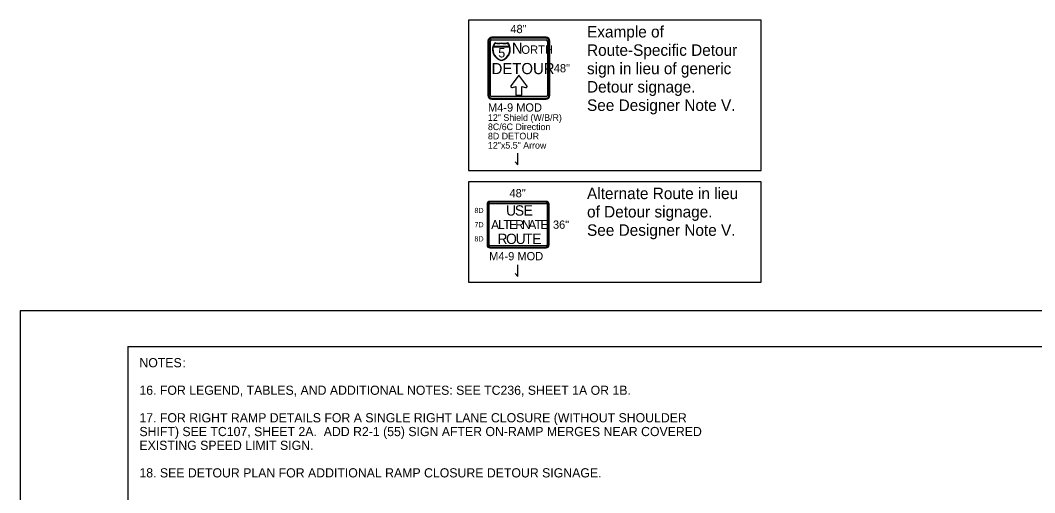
# Model space of a CAD drawing. Extents: x 99999 to 100116, y 99995 to 100013.
# Drawn here: x 100039.06 to 100047.9, y 100009.1 to 100013.22 of the extents above; entities that cross this region are included whole.
import ezdxf

# ---------------------------------------------------------------- set-up
doc = ezdxf.new("R2010")
doc.units = 0
for name, color, linetype in [('SH_GI_GeneralNotesBodyText', 7, 'Continuous'), ('SH_GI_PlotLimits', 7, 'Continuous'), ('SH_GI_SheetBorder', 7, 'Continuous'), ('TR_SN_ConstructionSigns', 7, 'Continuous'), ('TR_WZ_WorkZoneDetails', 7, 'Continuous')]:
    doc.layers.add(name, color=color, linetype=linetype)

msp = doc.modelspace()

# ---------------------------------------------------------------- linework, layer by layer
at = {"layer": 'SH_GI_PlotLimits'}
msp.add_lwpolyline([(100039.0625, 99999.6875), (100056.0625, 99999.6875), (100056.0625, 100010.6875), (100039.0625, 100010.6875)], close=True, dxfattribs=at)
at = {"layer": 'SH_GI_SheetBorder'}
for q in [(100040, 100000), (100055.75, 100010.375)]:
    msp.add_line((100040, 100010.375), q, dxfattribs=at)
at = {"layer": 'TR_SN_ConstructionSigns'}
for p, q in [((100043.1354, 100013.0373), (100043.1354, 100012.5648)), ((100043.1438, 100013.0373), (100043.1438, 100012.5648)), ((100043.1579, 100012.5648), (100043.1579, 100013.0373)), ((100043.6416, 100013.0711), (100043.1691, 100013.0711)), ((100043.6416, 100013.0626), (100043.1691, 100013.0626)), ((100043.1691, 100013.0486), (100043.6416, 100013.0486)), ((100043.6529, 100013.0373), (100043.6529, 100012.5648)), ((100043.6669, 100012.5648), (100043.6669, 100013.0373)), ((100043.6754, 100012.5648), (100043.6754, 100013.0373)), ((100043.3228, 100012.9875), (100043.1823, 100012.9875)), ((100043.1823, 100012.9875), (100043.3228, 100012.9875)), ((100043.1834, 100012.9912), (100043.3217, 100012.9912)), ((100043.3217, 100012.9912), (100043.1834, 100012.9912)), ((100043.6416, 100012.5536), (100043.1691, 100012.5536)), ((100043.1691, 100012.5395), (100043.6416, 100012.5395)), ((100043.1691, 100012.5311), (100043.6416, 100012.5311)), ((100043.6424, 100011.6405), (100043.153, 100011.6405)), ((100043.6424, 100011.6335), (100043.153, 100011.6335)), ((100043.153, 100011.6236), (100043.6424, 100011.6236)), ((100043.1277, 100011.6152), (100043.1277, 100011.2608)), ((100043.1347, 100011.6152), (100043.1347, 100011.2608)), ((100043.1446, 100011.2608), (100043.1446, 100011.6152)), ((100043.6508, 100011.6152), (100043.6508, 100011.2608)), ((100043.6607, 100011.2608), (100043.6607, 100011.6152)), ((100043.6677, 100011.2608), (100043.6677, 100011.6152)), ((100043.6424, 100011.2524), (100043.153, 100011.2524)), ((100043.153, 100011.2425), (100043.6424, 100011.2425)), ((100043.153, 100011.2355), (100043.6424, 100011.2355))]:
    msp.add_line(p, q, dxfattribs=at)
msp.add_lwpolyline([(100043.3367, 100012.6494), (100043.3356, 100012.6478), (100043.335, 100012.6461), (100043.3347, 100012.6441), (100043.3348, 100012.6424), (100043.335, 100012.6412), (100043.3356, 100012.6398), (100043.3373, 100012.6375), (100043.3386, 100012.6364), (100043.34, 100012.6355), (100043.3417, 100012.6348), (100043.3432, 100012.6345), (100043.3447, 100012.6343), (100043.3465, 100012.6343), (100043.3478, 100012.6346), (100043.3795, 100012.6424), (100043.3795, 100012.5671), (100043.4307, 100012.5671), (100043.4307, 100012.6429), (100043.4617, 100012.6337), (100043.4647, 100012.6331), (100043.4681, 100012.6334), (100043.4703, 100012.6342), (100043.4733, 100012.6362), (100043.4752, 100012.6389), (100043.476, 100012.6414), (100043.4761, 100012.6436), (100043.4754, 100012.6463), (100043.4746, 100012.6477), (100043.4051, 100012.7405), (100043.3367, 100012.6494)], dxfattribs=at)
for centre, radius, start, end in [((100043.1691, 100013.0373), 0.0337, 90, 180), ((100043.1691, 100013.0373), 0.0253, 90, 180), ((100043.1691, 100013.0373), 0.0113, 90, 180), ((100043.6416, 100013.0373), 0.0338, 360, 90), ((100043.6416, 100013.0373), 0.0253, 360, 90), ((100043.6416, 100013.0373), 0.0113, 360, 90), ((100043.2725, 100012.9642), 0.0973, 142.16169, 258.18105), ((100043.2715, 100012.9633), 0.0925, 164.85517, 258.18105), ((100043.2715, 100012.9633), 0.0925, 164.85517, 258.18105), ((100043.2715, 100012.9633), 0.0925, 142.16169, 162.48397), ((100043.2715, 100012.9633), 0.0925, 142.16169, 162.48397), ((100043.2245, 100013.1212), 0.1014, 253.48525, 286.04538), ((100043.2259, 100013.1124), 0.0964, 253.48525, 286.04538), ((100043.2259, 100013.1124), 0.0964, 253.48525, 286.04538), ((100043.2806, 100013.1212), 0.1014, 253.95462, 286.51475), ((100043.2792, 100013.1124), 0.0964, 253.95462, 286.51475), ((100043.2792, 100013.1124), 0.0964, 253.95462, 286.51475), ((100043.2325, 100012.9642), 0.0974, 281.90384, 37.84925), ((100043.2335, 100012.9633), 0.0925, 281.90384, 15.1558), ((100043.2335, 100012.9633), 0.0925, 281.90384, 15.1558), ((100043.2335, 100012.9633), 0.0925, 17.52691, 37.84925), ((100043.2335, 100012.9633), 0.0925, 17.52691, 37.84925), ((100043.1691, 100012.5648), 0.0338, 180, 270), ((100043.1691, 100012.5648), 0.0253, 180, 270), ((100043.1691, 100012.5648), 0.0113, 180, 270), ((100043.6416, 100012.5648), 0.0337, 270, 360), ((100043.6416, 100012.5648), 0.0253, 270, 0), ((100043.6416, 100012.5648), 0.0113, 270, 0), ((100043.153, 100011.6152), 0.0253, 90, 180), ((100043.153, 100011.6152), 0.0183, 90, 180), ((100043.153, 100011.6152), 0.00844, 90, 180), ((100043.6424, 100011.6152), 0.0253, 360, 90), ((100043.6424, 100011.6152), 0.0183, 360, 90), ((100043.6424, 100011.6152), 0.00844, 360, 90), ((100043.153, 100011.2608), 0.0253, 180, 270), ((100043.153, 100011.2608), 0.0183, 180, 270), ((100043.153, 100011.2608), 0.00844, 180, 270), ((100043.6424, 100011.2608), 0.0253, 270, 360), ((100043.6424, 100011.2608), 0.0183, 270, 0), ((100043.6424, 100011.2608), 0.00844, 270, 0)]:
    msp.add_arc(centre, radius, start, end, dxfattribs=at)
at = {"layer": 'TR_WZ_WorkZoneDetails'}
for p, q in [((100043.3963, 100011.9605), (100043.3963, 100012.0605)), ((100043.3713, 100011.9855), (100043.3963, 100011.9605)), ((100043.3963, 100010.9875), (100043.3963, 100011.0875)), ((100043.3713, 100011.0125), (100043.3963, 100010.9875))]:
    msp.add_line(p, q, dxfattribs=at)
for points in [[(100042.9666, 100011.9105), (100045.5143, 100011.9105), (100045.5143, 100013.2191), (100042.9666, 100013.2191)], [(100042.9666, 100010.9375), (100045.5143, 100010.9375), (100045.5143, 100011.8105), (100042.9666, 100011.8105)]]:
    msp.add_lwpolyline(points, close=True, dxfattribs=at)

# ---------------------------------------------------------------- texts
at = {"layer": 'SH_GI_GeneralNotesBodyText'}
for s, p in [('NOTES', (100040.1, 100010.195)), (':', (100040.4743, 100010.195)), ('16. FOR LEGEND, TABLES, AND ADDITIONAL NOTES: SEE TC236, SHEET 1A OR 1B.', (100040.1, 100009.955)), ('17. FOR RIGHT RAMP DETAILS FOR A SINGLE RIGHT LANE CLOSURE (WITHOUT SHOULDER ', (100040.1, 100009.715)), ('SHIFT) SEE TC107, SHEET 2A.  ADD R2-1 (55) SIGN AFTER ON-RAMP MERGES NEAR COVERED ', (100040.1, 100009.595)), ('EXISTING SPEED LIMIT SIGN.', (100040.1, 100009.475)), ('18. SEE DETOUR PLAN FOR ADDITIONAL RAMP CLOSURE DETOUR SIGNAGE.', (100040.1, 100009.235))]:
    msp.add_text(s, height=0.08, rotation=360, dxfattribs=at).set_placement(p)
at = {"layer": 'TR_SN_ConstructionSigns'}
for s, height, p in [('48"', 0.072, (100043.3306, 100013.1071)), ('5', 0.081, (100043.2253, 100012.8951)), ('N', 0.0972, (100043.3432, 100012.9267)), ('ORTH', 0.0729, (100043.4264, 100012.9267)), ('DETOUR', 0.0972, (100043.1668, 100012.7497)), ('48"', 0.072, (100043.7086, 100012.7651)), ('M4-9 MOD', 0.072, (100043.1354, 100012.4231)), ('12" Shield (W/B/R)', 0.0576, (100043.1354, 100012.3424)), ('8C/6C Direction', 0.0576, (100043.1354, 100012.2618)), ('8D DETOUR', 0.0576, (100043.1354, 100012.1811)), ('12"x5.5" Arrow', 0.0576, (100043.1354, 100012.1005)), ('48"', 0.072, (100043.323, 100011.6765)), ('36"', 0.072, (100043.7015, 100011.402)), ('M4-9 MOD', 0.072, (100043.1457, 100011.1275))]:
    msp.add_text(s, height=height, rotation=360, dxfattribs=at).set_placement(p)
for s, height, p in [('8D', 0.045, (100043.018, 100011.5392)), ('U', 0.09, (100043.2933, 100011.5167)), ('S', 0.09, (100043.3698, 100011.5167)), ('E', 0.09, (100043.4463, 100011.5167)), ('7D', 0.045, (100043.018, 100011.4155)), ('A', 0.0787, (100043.1626, 100011.3986)), ('L', 0.0787, (100043.2241, 100011.3986)), ('T', 0.0787, (100043.269, 100011.3986)), ('E', 0.0787, (100043.3201, 100011.3986)), ('R', 0.0787, (100043.3737, 100011.3986)), ('N', 0.0787, (100043.4312, 100011.3986)), ('A', 0.0787, (100043.4863, 100011.3986)), ('T', 0.0787, (100043.5414, 100011.3986)), ('E', 0.0787, (100043.5926, 100011.3986)), ('R', 0.09, (100043.2186, 100011.2692)), ('O', 0.09, (100043.2933, 100011.2692)), ('U', 0.09, (100043.377, 100011.2692)), ('T', 0.09, (100043.4517, 100011.2692)), ('E', 0.09, (100043.521, 100011.2692)), ('8D', 0.045, (100043.018, 100011.2917))]:
    msp.add_text(s, height=height, dxfattribs=at).set_placement(p)
at = {"layer": 'TR_WZ_WorkZoneDetails'}
for s, p in [('Example of ', (100043.9983, 100013.0691)), ('Route-Specific Detour ', (100043.9983, 100012.9091)), ('sign in lieu of generic ', (100043.9983, 100012.7491)), ('Detour signage.', (100043.9983, 100012.5891)), ('See Designer Note V.', (100043.9983, 100012.4291)), ('Alternate Route in lieu ', (100043.9983, 100011.6605)), ('of Detour signage.', (100043.9983, 100011.5005)), ('See Designer Note V.', (100043.9983, 100011.3405))]:
    msp.add_text(s, height=0.1, dxfattribs=at).set_placement(p)

doc.saveas('drawing.dxf')
